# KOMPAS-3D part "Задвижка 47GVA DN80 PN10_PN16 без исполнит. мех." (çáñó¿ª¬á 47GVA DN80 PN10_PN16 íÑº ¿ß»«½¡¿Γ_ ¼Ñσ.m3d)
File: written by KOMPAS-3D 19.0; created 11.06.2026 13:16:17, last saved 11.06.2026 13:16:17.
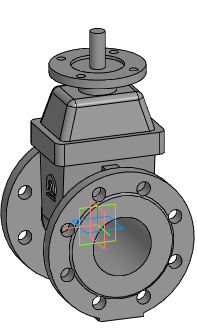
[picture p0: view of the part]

Document properties: Автор: Евгений; Полное имя файла: Z:\3.Личные\kachalov\001_3d для проектировщиков\2.2 Тип 47GVA, 47GVA.Z\_stp\_stp_Задвижка 47GVA DN40-DN1000 без исп.мех\Задвижка 47GVA DN80 PN10_PN16 без исполнит_ мех.m3d

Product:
- Part/product: Задвижка 47GVA DN80 PN10_PN16 без исполнит. мех.

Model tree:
1. Операция без истории:1  (labels: Задвижка 47GVA DN80 PN10_PN16 без исполнит. мех.)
